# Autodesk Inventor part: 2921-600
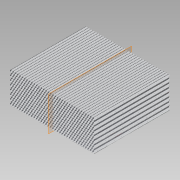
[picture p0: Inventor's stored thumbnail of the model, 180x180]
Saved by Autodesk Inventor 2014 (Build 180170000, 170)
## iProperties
Company: NHTSA/VRTC
Created: 2012-02
Part Number: 2921-600
Project: CHILD SIDE IMPACT SLED
Material: Aluminum-6061
Description: HONEYCOMB
Document SubType Name: Modeling
Designer: Mike Vanvoorhis
Mass: 812.653 g
Surface Area: 87688.7 cm^2
Volume: 299.872 cm^3
Density: 2.71 g/cm^3
Catalog Web Link: http://www.plascore.com
Vendor: Plascore, Inc.
Stock Number: 3/8" CELL SIZE - .0015 FOIL GAGE - DENSITY: 2.3 PCF
Appearance: Aluminum - Polished
Material Specs: 3/8" CELL SIZE - .0015 FOIL GAGE
Title: HONEYCOMB
Subject: Child Side Impact Sled
Author: Dave Walker
Comments: Aluminum Honeycomb Part #PAMG-XR1-2.3-3/8-0015-P-5052 Plascore, Inc. Zeeland, MI. (616)748-2252
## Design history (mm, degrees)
sketch "Sketch1"
  geometry: L1 (0, 13.198)-(0, -2.2) reference; L2 (-5.715, 0)-(0.952, 0) reference; L3 (0, 0)-(-4.762, 2.75); L4 (-4.762, 2.75)-(-4.762, 8.249); L5 (-4.762, 8.249)-(0, 10.999)
  constraints: 6 end point, 1 equal length, 1 perpendicular, 1 point on line
  dimensions: "d6" = 30 deg angle of L2 L3; "d8" = 60 deg angle of L5 L1; "d15" = 4.7625 distance from line of L4 L3.start (= 0.5 x d14)
extrude "Extrusion1" new body sketch "Sketch1" distance "d17" = 305; taper "d18" = 0 deg
mirror "Mirror1"
sketch "Sketch2"
  geometry: L1 (2.381, 8.249)-(-2.381, 10.999); L2 (-2.381, 10.999)-(-2.381, 16.498); L3 (-2.381, 16.498)-(2.381, 19.247); L4 (-2.381, 10.999)-(2.381, 8.249) reference; L5 (2.381, 8.249)-(2.381, 2.75) reference; L6 (2.381, 19.247)-(2.381, 8.249)
  constraints: 8 end point, 3 equal length
  dimensions: "d20" = 4.7625 distance from line of L2 L1.start (= 0.5 x d25); "d26" = 120 deg angle of L1 L5; "d27" = 120 deg angle of L3 L2 (= d26)
extrude "Extrusion2" new body sketch "Sketch2" taper "d23" = 0 deg; distance "d24" = 305
mirror "Mirror2"
sketch "Sketch3"
  geometry: L1 (4.762, 19.247)-(0, 16.498) reference; L2 (4.762, 19.247)-(9.525, 16.498) reference; L3 (9.525, 16.498)-(9.525, 10.999) reference; L4 (9.525, 10.999)-(4.762, 8.249) reference; L5 (4.762, 2.75)-(4.762, 8.249) reference; L6 (4.762, 2.75)-(0, 0) reference; L7 (-4.762, 2.75)-(0, 0) reference; L8 (-4.762, 8.249)-(-4.762, 2.75) reference; L9 (0, 10.999)-(-4.762, 8.249) reference; L10 (0, 16.498)-(0, 10.999) reference; L11 (0.038, 16.476)-(4.762, 19.203); L12 (4.762, 19.203)-(9.487, 16.476); L13 (9.487, 16.476)-(9.487, 11.021); L14 (9.487, 11.021)-(4.743, 8.282); L15 (4.724, 8.249)-(4.724, 2.772); L16 (4.724, 2.772)-(0, 0.044); L17 (0, 0.044)-(-4.724, 2.772); L18 (-4.724, 2.772)-(-4.724, 8.227); L19 (-4.724, 8.227)-(0.019, 10.966); L20 (0.038, 10.999)-(0.038, 16.476); L21 (0.038, 10.999)-(4.743, 8.282); L22 (0.019, 10.966)-(4.724, 8.249)
  constraints: 24 end point, 2 parallel, 5 other
  dimensions: "d28" = 0.0381 distance between parallel lines of L11 L1; "d30" = 0.0381 distance between parallel lines of L7 L17; "d31" = 0.0381 distance between parallel lines of L9 L19; "d32" = 0.0381 distance between parallel lines of L5 L15 (= d30); "d33" = 0.0381 distance between parallel lines of L10 L20 (= d30); "d38" = 0.0381 distance between parallel lines of L22 L21; "d39" = 0.01905 distance from line of L21 L9.start (= 0.5 x d38)
extrude "Extrusion3" cut sketch "Sketch3" stored distance "d36" = 305; taper "d37" = 0 deg
sketch "Sketch4"
  geometry: L1 (-4.762, 184.225)-(400.05, 184.225); L2 (337.238, 127)-(-4.762, 127); L3 (-4.762, 127)-(-4.762, 184.225); L4 (337.238, 0)-(400.05, 0); L5 (400.05, 0)-(400.05, 184.225); L6 (337.238, 127)-(337.238, 0); L7 (-4.762, 8.249)-(-4.762, 2.75) reference; L8 (-4.762, 173.227)-(-4.762, 167.727) reference; L9 (400.05, 16.498)-(400.05, 10.999) reference; 2 further points
  constraints: 12 end point, 2 collinear, 2 horizontal, 2 parallel, 2 point on line
  dimensions: "d46" = 127 distance from line of L2 point (0, 0); "d47" = 342 distance between parallel lines of L6 L7
extrude "Extrusion4" cut sketch "Sketch4" stored distance "d48" = 0; taper "d49" = 0 deg
workplane "Work Plane1"
workplane "Work Plane2 - Y Axis Mid Plane"
body "Solid1"
pattern_linear "Rectangular Pattern1" dims "d42" = 9.525, "d45" = 16.49778
other parameters: "d14" = 9.525, "d25" = 9.525, "d51" = 166.24
